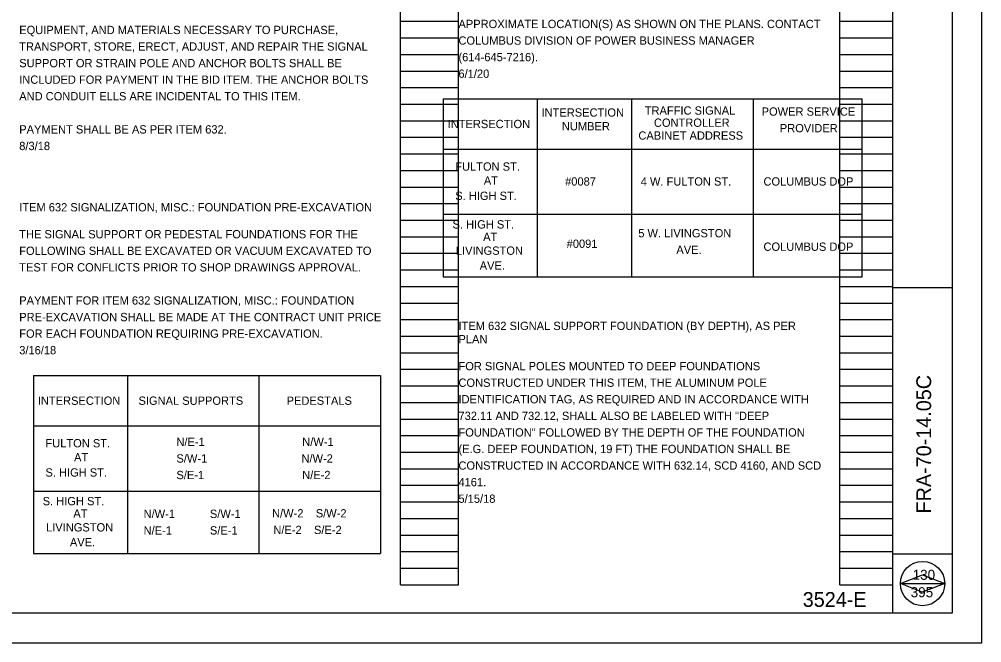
# Model space of a CAD drawing. Extents: x -27 to 74, y -37 to 38.
# Drawn here: x 17.23 to 33.49, y -7.51 to 3.03 of the extents above; entities that cross this region are included whole.
import ezdxf

# ---------------------------------------------------------------- set-up
doc = ezdxf.new("R2010")
doc.units = 0
for name, color, linetype in [('Level 63', 7, 'Continuous'), ('PF_P_Text', 7, 'Continuous'), ('SC_Scratch1', 7, 'Continuous'), ('SH_Cut_Line', 7, 'Continuous'), ('SH_Data', 7, 'Continuous'), ('SH_Text', 7, 'Continuous'), ('SN_P_Text', 7, 'Continuous')]:
    doc.layers.add(name, color=color, linetype=linetype)

msp = doc.modelspace()

# ---------------------------------------------------------------- linework, layer by layer
at = {"layer": 'Level 63'}
msp.add_line((32.119, -6.508), (32.869, -6.508), dxfattribs=at)
msp.add_circle((32.494, -6.508), 0.375, dxfattribs=at)
at = {"layer": 'PF_P_Text'}
for p, q in [((31.994, -7.008), (31.994, 13.992)), ((31.994, -1.508), (32.994, -1.508)), ((31.994, -6.008), (32.994, -6.008))]:
    msp.add_line(p, q, dxfattribs=at)
msp.add_lwpolyline([(1.494, 13.992), (32.994, 13.992), (32.994, -7.008), (1.494, -7.008)], close=True, dxfattribs=at)
at = {"layer": 'SC_Scratch1'}
for p, q in [((23.674, -6.528), (23.674, 13.632)), ((24.654, -6.528), (24.654, 13.632)), ((31.094, -6.528), (31.094, 13.632)), ((31.994, -6.528), (31.994, 13.632)), ((23.674, 2.992), (24.654, 2.992)), ((31.094, 2.992), (31.994, 2.992)), ((23.674, 2.712), (24.654, 2.712)), ((31.094, 2.712), (31.994, 2.712)), ((23.674, 2.432), (24.654, 2.432)), ((31.094, 2.432), (31.994, 2.432)), ((23.674, 2.152), (24.654, 2.152)), ((31.094, 2.152), (31.994, 2.152)), ((23.674, 1.872), (24.654, 1.872)), ((31.094, 1.872), (31.994, 1.872)), ((23.674, 1.592), (24.654, 1.592)), ((31.094, 1.592), (31.994, 1.592)), ((23.674, 1.312), (24.654, 1.312)), ((31.094, 1.312), (31.994, 1.312)), ((23.674, 1.032), (24.654, 1.032)), ((31.094, 1.032), (31.994, 1.032)), ((23.674, 0.752), (24.654, 0.752)), ((31.094, 0.752), (31.994, 0.752)), ((23.674, 0.472), (24.654, 0.472)), ((31.094, 0.472), (31.994, 0.472)), ((23.674, 0.192), (24.654, 0.192)), ((31.094, 0.192), (31.994, 0.192)), ((23.674, -0.088), (24.654, -0.088)), ((31.094, -0.088), (31.994, -0.088)), ((23.674, -0.368), (24.654, -0.368)), ((31.094, -0.368), (31.994, -0.368)), ((23.674, -0.648), (24.654, -0.648)), ((31.094, -0.648), (31.994, -0.648)), ((23.674, -0.928), (24.654, -0.928)), ((31.094, -0.928), (31.994, -0.928)), ((23.674, -1.208), (24.654, -1.208)), ((31.094, -1.208), (31.994, -1.208)), ((23.674, -1.488), (24.654, -1.488)), ((31.094, -1.488), (31.994, -1.488)), ((23.674, -1.768), (24.654, -1.768)), ((31.094, -1.768), (31.994, -1.768)), ((23.674, -2.048), (24.654, -2.048)), ((31.094, -2.048), (31.994, -2.048)), ((23.674, -2.328), (24.654, -2.328)), ((31.094, -2.328), (31.994, -2.328)), ((23.674, -2.608), (24.654, -2.608)), ((31.094, -2.608), (31.994, -2.608)), ((23.674, -2.888), (24.654, -2.888)), ((31.094, -2.888), (31.994, -2.888)), ((23.674, -3.168), (24.654, -3.168)), ((31.094, -3.168), (31.994, -3.168)), ((23.674, -3.448), (24.654, -3.448)), ((31.094, -3.448), (31.994, -3.448)), ((23.674, -3.728), (24.654, -3.728)), ((31.094, -3.728), (31.994, -3.728)), ((23.674, -4.008), (24.654, -4.008)), ((31.094, -4.008), (31.994, -4.008)), ((23.674, -4.288), (24.654, -4.288)), ((31.094, -4.288), (31.994, -4.288)), ((23.674, -4.568), (24.654, -4.568)), ((31.094, -4.568), (31.994, -4.568)), ((23.674, -4.848), (24.654, -4.848)), ((31.094, -4.848), (31.994, -4.848)), ((23.674, -5.128), (24.654, -5.128)), ((31.094, -5.128), (31.994, -5.128)), ((23.674, -5.408), (24.654, -5.408)), ((31.094, -5.408), (31.994, -5.408)), ((23.674, -5.688), (24.654, -5.688)), ((31.094, -5.688), (31.994, -5.688)), ((23.674, -5.968), (24.654, -5.968)), ((31.094, -5.968), (31.994, -5.968)), ((23.674, -6.248), (24.654, -6.248)), ((31.094, -6.248), (31.994, -6.248)), ((32.119, -6.508), (32.495, -6.36)), ((32.495, -6.36), (32.869, -6.508)), ((23.674, -6.528), (24.654, -6.528)), ((31.094, -6.528), (31.994, -6.528)), ((32.49, -6.654), (32.119, -6.508)), ((32.869, -6.508), (32.49, -6.654))]:
    msp.add_line(p, q, dxfattribs=at)
at = {"layer": 'SH_Cut_Line'}
msp.add_lwpolyline([(-0.506, -7.508), (33.494, -7.508), (33.494, 14.492), (-0.506, 14.492)], close=True, dxfattribs=at)
at = {"layer": 'SH_Text'}
for p, q in [((24.398, 1.682), (24.398, -1.327)), ((24.398, 1.682), (31.474, 1.682)), ((25.984, 1.682), (25.984, -1.327)), ((27.575, 1.682), (27.575, -1.327)), ((29.63, 1.682), (29.63, -1.327)), ((31.474, -1.327), (31.474, 1.682)), ((24.398, 0.832), (31.474, 0.832)), ((24.398, -0.269), (31.474, -0.269)), ((24.398, -1.327), (31.474, -1.327)), ((17.475, -2.993), (23.336, -2.993)), ((17.475, -2.993), (17.475, -6.002)), ((19.061, -2.993), (19.061, -6.002)), ((21.282, -2.993), (21.282, -6.002)), ((23.336, -2.993), (23.336, -6.002)), ((17.475, -3.843), (23.336, -3.843)), ((17.475, -4.945), (23.336, -4.945)), ((17.475, -6.002), (23.336, -6.002))]:
    msp.add_line(p, q, dxfattribs=at)

# ---------------------------------------------------------------- texts
at = {"layer": 'SH_Data'}
for s, p in [('APPROXIMATE LOCATION(S) AS SHOWN ON THE PLANS. CONTACT ', (24.654, 2.877)), ('COLUMBUS DIVISION OF POWER BUSINESS MANAGER ', (24.654, 2.597)), ('(614-645-7216).', (24.654, 2.317)), ('6/1/20', (24.654, 2.037)), ('INTERSECTION', (26.057, 1.381)), ('TRAFFIC SIGNAL', (27.801, 1.415)), ('POWER SERVICE ', (29.776, 1.397)), ('INTERSECTION', (24.471, 1.187)), ('CONTROLLER', (27.956, 1.209)), ('NUMBER', (26.401, 1.149)), ('PROVIDER', (30.083, 1.117)), ('CABINET ADDRESS', (27.694, 0.992)), ('FULTON ST.', (24.6, 0.468)), ('AT', (25.083, 0.232)), ('#0087', (26.456, 0.216)), ('4 W. FULTON ST.', (27.733, 0.216)), ('COLUMBUS DOP', (29.807, 0.216)), ('S. HIGH ST.', (24.6, -0.026)), ('ITEM 632 SIGNALIZATION, MISC.: FOUNDATION PRE-EXCAVATION', (17.234, -0.22)), ('S. HIGH ST. ', (24.554, -0.509)), ('THE SIGNAL SUPPORT OR PEDESTAL FOUNDATIONS FOR THE ', (17.234, -0.675)), ('AT', (25.071, -0.719)), ('5 W. LIVINGSTON ', (27.692, -0.658)), ('FOLLOWING SHALL BE EXCAVATED OR VACUUM EXCAVATED TO ', (17.234, -0.955)), ('LIVINGSTON', (24.61, -0.953)), ('#0091', (26.482, -0.836)), ('AVE.', (28.335, -0.938)), ('COLUMBUS DOP', (29.807, -0.886)), ('TEST FOR CONFLICTS PRIOR TO SHOP DRAWINGS APPROVAL. ', (17.234, -1.235)), ('AVE.', (25.013, -1.205)), ('PAYMENT FOR ITEM 632 SIGNALIZATION, MISC.: FOUNDATION ', (17.234, -1.795)), ('PRE-EXCAVATION SHALL BE MADE AT THE CONTRACT UNIT PRICE ', (17.234, -2.075)), ('ITEM 632 SIGNAL SUPPORT FOUNDATION (BY DEPTH), AS PER ', (24.654, -2.224)), ('FOR EACH FOUNDATION REQUIRING PRE-EXCAVATION. ', (17.234, -2.355)), ('PLAN', (24.654, -2.449)), ('3/16/18', (17.234, -2.635)), ('FOR SIGNAL POLES MOUNTED TO DEEP FOUNDATIONS ', (24.654, -2.904)), ('CONSTRUCTED UNDER THIS ITEM, THE ALUMINUM POLE ', (24.654, -3.184)), ('INTERSECTION', (17.548, -3.488)), ('SIGNAL SUPPORTS', (19.249, -3.488)), ('PEDESTALS', (21.751, -3.488)), ('IDENTIFICATION TAG, AS REQUIRED AND IN ACCORDANCE WITH ', (24.654, -3.464)), ('732.11 AND 732.12, SHALL ALSO BE LABELED WITH "DEEP ', (24.654, -3.744)), ('FOUNDATION" FOLLOWED BY THE DEPTH OF THE FOUNDATION ', (24.654, -4.024)), ('N/E-1', (19.89, -4.184)), ('N/W-1', (22.015, -4.184)), ('FULTON ST.', (17.677, -4.207)), ('(E.G. DEEP FOUNDATION, 19 FT) THE FOUNDATION SHALL BE ', (24.654, -4.304)), ('AT', (18.16, -4.444)), ('S/W-1', (19.89, -4.464)), ('N/W-2', (22.002, -4.464)), ('CONSTRUCTED IN ACCORDANCE WITH 632.14, SCD 4160, AND SCD ', (24.654, -4.584)), ('S. HIGH ST.', (17.677, -4.701)), ('S/E-1', (19.89, -4.744)), ('N/E-2', (22.014, -4.744)), ('4161.', (24.654, -4.864)), ('5/15/18', (24.654, -5.144)), ('S. HIGH ST. ', (17.63, -5.185)), ('AT', (18.148, -5.394)), ('N/W-1', (19.335, -5.4)), ('S/W-1', (20.455, -5.4)), ('N/W-2    S/W-2', (21.505, -5.391)), ('LIVINGSTON', (17.687, -5.628)), ('N/E-2    S/E-2', (21.527, -5.671)), ('N/E-1', (19.335, -5.68)), ('S/E-1', (20.455, -5.68)), ('AVE.', (18.09, -5.88))]:
    msp.add_text(s, height=0.14, dxfattribs=at).set_placement(p)
at = {"layer": 'SH_Text'}
for s, rotation, p in [('FRA-70-14.05C', 90, (32.639, -5.324)), ('3524-E', 359.9999, (30.47, -6.902))]:
    msp.add_text(s, height=0.25, rotation=rotation, dxfattribs=at).set_placement(p)
for s, p in [('130', (32.327, -6.445)), ('395', (32.294, -6.739))]:
    msp.add_text(s, height=0.17, dxfattribs=at).set_placement(p)
at = {"layer": 'SN_P_Text'}
for s, p in [('EQUIPMENT, AND MATERIALS NECESSARY TO PURCHASE, ', (17.234, 2.776)), ('TRANSPORT, STORE, ERECT, ADJUST, AND REPAIR THE SIGNAL ', (17.234, 2.496)), ('SUPPORT OR STRAIN POLE AND ANCHOR BOLTS SHALL BE ', (17.234, 2.216)), ('INCLUDED FOR PAYMENT IN THE BID ITEM. THE ANCHOR BOLTS ', (17.234, 1.936)), ('AND CONDUIT ELLS ARE INCIDENTAL TO THIS ITEM.', (17.234, 1.656)), ('PAYMENT SHALL BE AS PER ITEM 632.', (17.234, 1.096)), ('8/3/18', (17.234, 0.816))]:
    msp.add_text(s, height=0.14, rotation=0, dxfattribs=at).set_placement(p)

doc.saveas('drawing.dxf')
